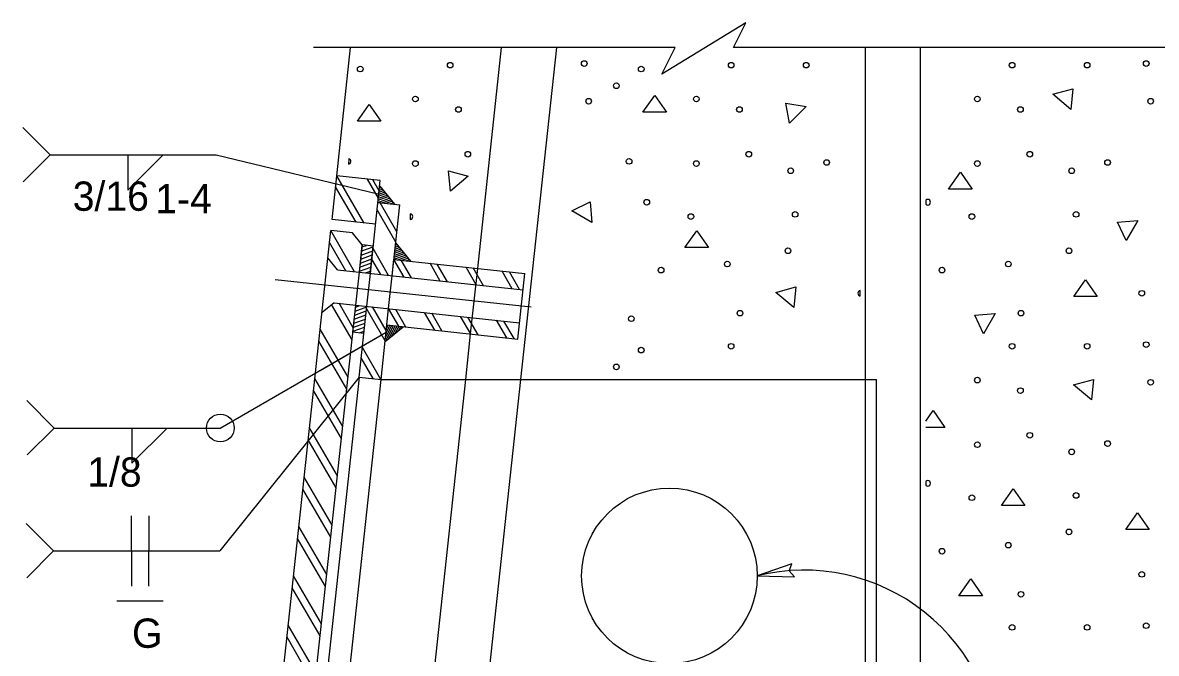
# Model space of a CAD drawing. Extents: x 0 to 2.83, y -0.03 to 1.83.
# Drawn here: x 2.1921 to 2.5956, y 0.6079 to 0.8323 of the extents above; entities that cross this region are included whole.
import ezdxf

# ---------------------------------------------------------------- set-up
doc = ezdxf.new("R2010")
doc.units = 0
for name, color, linetype in [('50', 7, 'Continuous'), ('51', 7, 'Continuous'), ('52', 7, 'Continuous'), ('54', 7, 'Continuous'), ('55', 7, 'Continuous'), ('57', 7, 'Continuous'), ('59', 7, 'Continuous')]:
    doc.layers.add(name, color=color, linetype=linetype)

msp = doc.modelspace()

# ---------------------------------------------------------------- linework, layer by layer
at = {"layer": '50'}
for p, q in [((2.3038940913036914, 0.7777618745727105), (2.3088182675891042, 0.8233925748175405)), ((2.3196378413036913, 0.7053306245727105), (2.4959440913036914, 0.7053306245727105)), ((2.4959440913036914, 0.4241493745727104), (2.4959440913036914, 0.7053306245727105))]:
    msp.add_line(p, q, dxfattribs=at)
for points in [[(2.558756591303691, 0.8067806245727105), (2.565806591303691, 0.8086806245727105), (2.5651565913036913, 0.8013806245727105), (2.558756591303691, 0.8067806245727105)], [(2.3113065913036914, 0.7971806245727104), (2.315456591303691, 0.8031306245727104), (2.319606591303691, 0.7971806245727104), (2.3113065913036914, 0.7971806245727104)], [(2.4128565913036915, 0.8003806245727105), (2.4170565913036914, 0.8063806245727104), (2.421206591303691, 0.8003806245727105), (2.4128565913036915, 0.8003806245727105)], [(2.4650565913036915, 0.7964806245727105), (2.4637565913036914, 0.8036806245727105), (2.4709565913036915, 0.8023806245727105), (2.4650565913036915, 0.7964806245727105)], [(2.308194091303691, 0.7838806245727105), (2.308019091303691, 0.7819181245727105)], [(2.3443065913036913, 0.7723306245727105), (2.343656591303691, 0.7795806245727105), (2.350706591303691, 0.7776806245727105), (2.3443065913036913, 0.7723306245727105)], [(2.5216565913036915, 0.7730806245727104), (2.5258565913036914, 0.7790806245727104), (2.530006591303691, 0.7730806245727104), (2.5216565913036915, 0.7730806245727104)], [(2.3875065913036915, 0.7653806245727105), (2.394106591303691, 0.7684806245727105), (2.394706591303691, 0.7612306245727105), (2.3875065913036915, 0.7653806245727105)], [(2.513500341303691, 0.7690931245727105), (2.513500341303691, 0.7676806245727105)], [(2.3300440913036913, 0.7642743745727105), (2.3300440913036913, 0.7622868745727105)], [(2.5848065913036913, 0.7547306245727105), (2.5817065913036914, 0.7613306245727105), (2.5889565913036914, 0.7619306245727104), (2.5848065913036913, 0.7547306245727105)], [(2.4278065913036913, 0.7522306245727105), (2.4320065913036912, 0.7582306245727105), (2.4361565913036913, 0.7522306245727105), (2.4278065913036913, 0.7522306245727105)], [(2.5661565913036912, 0.7348306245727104), (2.5703065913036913, 0.7408306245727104), (2.5745065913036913, 0.7348306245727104), (2.5661565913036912, 0.7348306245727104)], [(2.4602065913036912, 0.7363306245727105), (2.4672565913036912, 0.7382306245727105), (2.4666065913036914, 0.7309806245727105), (2.4602065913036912, 0.7363306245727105)], [(2.4901503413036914, 0.7350181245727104), (2.490169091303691, 0.7369681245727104)], [(2.5341065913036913, 0.7215806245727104), (2.5310065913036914, 0.7281806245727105), (2.5382565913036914, 0.7287806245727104), (2.5341065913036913, 0.7215806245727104)], [(2.5661065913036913, 0.7034306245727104), (2.5731565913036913, 0.7053306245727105), (2.5725065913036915, 0.6980806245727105), (2.5661065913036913, 0.7034306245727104)], [(2.513500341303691, 0.6905118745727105), (2.5161065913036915, 0.6942806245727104), (2.520256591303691, 0.6882806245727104), (2.513500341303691, 0.6882806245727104)], [(2.513500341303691, 0.6690931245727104), (2.513500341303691, 0.6676806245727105)], [(2.540456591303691, 0.6604806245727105), (2.5446065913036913, 0.6664306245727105), (2.5487565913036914, 0.6604806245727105), (2.540456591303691, 0.6604806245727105)], [(2.5847065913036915, 0.6519806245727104), (2.5889065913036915, 0.6579306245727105), (2.593056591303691, 0.6519806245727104), (2.5847065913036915, 0.6519806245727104)], [(2.5253065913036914, 0.6283806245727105), (2.5295065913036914, 0.6343806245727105), (2.5336565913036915, 0.6283806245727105), (2.5253065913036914, 0.6283806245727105)]]:
    msp.add_lwpolyline(points, dxfattribs=at)
for centre in [(2.31224447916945, 0.8157648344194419), (2.34424947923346, 0.8171390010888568), (2.3919628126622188, 0.8177281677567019), (2.412244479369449, 0.8157648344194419), (2.444249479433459, 0.8171390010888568), (2.4709536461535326, 0.8171390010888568), (2.5442494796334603, 0.8171390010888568), (2.5709536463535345, 0.8171390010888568), (2.591962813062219, 0.8177281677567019), (2.4034086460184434, 0.809816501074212), (2.331879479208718, 0.8051040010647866), (2.3935336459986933, 0.8043190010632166), (2.4318794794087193, 0.8051040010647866), (2.531879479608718, 0.8051040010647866), (2.5935336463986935, 0.8043190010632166), (2.347195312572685, 0.8013731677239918), (2.4471953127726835, 0.8013731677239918), (2.547195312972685, 0.8013731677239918), (2.331879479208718, 0.7821315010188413), (2.3505328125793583, 0.7854690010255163), (2.4079244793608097, 0.7829165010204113), (2.4318794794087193, 0.7821315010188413), (2.45053281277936, 0.7854690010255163), (2.478218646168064, 0.7825240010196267), (2.531879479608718, 0.7821315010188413), (2.5505328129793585, 0.7854690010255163), (2.5782186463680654, 0.7825240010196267), (2.465455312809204, 0.7795781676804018), (2.5654553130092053, 0.7795781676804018), (2.414207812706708, 0.7683865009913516), (2.4299161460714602, 0.7632815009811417), (2.4670261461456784, 0.7640665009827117), (2.5299161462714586, 0.7632815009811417), (2.56702614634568, 0.7640665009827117), (2.464473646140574, 0.7511081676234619), (2.5644736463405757, 0.7511081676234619), (2.4428753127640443, 0.7463956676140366), (2.542875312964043, 0.7463956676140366), (2.4193128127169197, 0.7442356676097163), (2.519312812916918, 0.7442356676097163), (2.5903919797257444, 0.7359890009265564), (2.4087103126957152, 0.7269565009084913), (2.447391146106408, 0.7289198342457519), (2.5473911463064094, 0.7289198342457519), (2.591962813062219, 0.7177281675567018), (2.412244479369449, 0.7157648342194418), (2.444249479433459, 0.7171390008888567), (2.5442494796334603, 0.7171390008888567), (2.5709536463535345, 0.7171390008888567), (2.4034086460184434, 0.7098165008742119), (2.531879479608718, 0.7051040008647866), (2.547195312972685, 0.7013731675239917), (2.5935336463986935, 0.7043190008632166), (2.5505328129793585, 0.6854690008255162), (2.531879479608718, 0.6821315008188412), (2.5782186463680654, 0.6825240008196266), (2.5654553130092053, 0.6795781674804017), (2.5299161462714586, 0.6632815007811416), (2.56702614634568, 0.6640665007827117), (2.5644736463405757, 0.6511081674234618), (2.542875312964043, 0.6463956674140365), (2.519312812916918, 0.6442356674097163), (2.5903919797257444, 0.6359890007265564), (2.5473911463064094, 0.6289198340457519), (2.5442494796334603, 0.6171390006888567), (2.5709536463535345, 0.6171390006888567), (2.591962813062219, 0.6177281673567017)]:
    msp.add_circle(centre, 0.0010011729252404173, dxfattribs=at)
for centre, start, end in [((2.3079244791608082, 0.7829165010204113), 275.39363055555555, 74.22253333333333), ((2.51420781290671, 0.7683865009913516), 225.03758611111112, 134.96241388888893), ((2.3299161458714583, 0.7632815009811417), 277.34222222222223, 82.65777500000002), ((2.490391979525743, 0.7359890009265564), 102.75421944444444, 256.04021111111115), ((2.51420781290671, 0.6683865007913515), 225.03758611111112, 134.96241388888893)]:
    msp.add_arc(centre, 0.0010011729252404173, start, end, dxfattribs=at)
at = {"layer": '51'}
for p, q in [((2.3623987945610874, 0.8233925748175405), (2.353919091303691, 0.7448368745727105)), ((2.382049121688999, 0.8233925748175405), (2.3693065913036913, 0.7053306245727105)), ((2.4919940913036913, 0.8233925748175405), (2.4919940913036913, 0.7053306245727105)), ((2.5115378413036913, 0.8233925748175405), (2.5115378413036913, 0.3265870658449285)), ((2.353919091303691, 0.7448368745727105), (2.3514065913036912, 0.7215431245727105)), ((2.3514065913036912, 0.7215431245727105), (2.3496565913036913, 0.7053306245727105)), ((2.3496565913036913, 0.7053306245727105), (2.3193003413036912, 0.4241493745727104)), ((2.3693065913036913, 0.7053306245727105), (2.338950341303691, 0.4241493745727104)), ((2.4919940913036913, 0.7053306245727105), (2.4919940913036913, 0.4241493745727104))]:
    msp.add_line(p, q, dxfattribs=at)
at = {"layer": '52'}
for p, q in [((2.3021940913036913, 0.7621868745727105), (2.3038940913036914, 0.7777618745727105)), ((2.3193878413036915, 0.7760618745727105), (2.3038940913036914, 0.7777618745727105)), ((2.3135815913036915, 0.7609806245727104), (2.3038940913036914, 0.7777618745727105)), ((2.3187128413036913, 0.7698368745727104), (2.314831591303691, 0.7765618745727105)), ((2.3158378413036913, 0.7430618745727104), (2.3193878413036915, 0.7760618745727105)), ((2.3189940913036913, 0.7724306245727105), (2.316731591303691, 0.7763493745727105)), ((2.310739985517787, 0.7612782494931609), (2.303468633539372, 0.7738639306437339)), ((2.3187065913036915, 0.7697868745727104), (2.3217690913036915, 0.7709056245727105)), ((2.318787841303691, 0.7705056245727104), (2.321344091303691, 0.7714368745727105)), ((2.3188628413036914, 0.7712306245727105), (2.3209128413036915, 0.7719681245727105)), ((2.3189440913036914, 0.7719431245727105), (2.3204815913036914, 0.7725056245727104)), ((2.319031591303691, 0.7726681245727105), (2.3200440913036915, 0.7730431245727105)), ((2.3191065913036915, 0.7733868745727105), (2.319619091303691, 0.7735806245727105)), ((2.3191878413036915, 0.7741118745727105), (2.3243878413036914, 0.7676618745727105)), ((2.3191878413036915, 0.7741118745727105), (2.3191878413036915, 0.7741118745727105)), ((2.3185378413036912, 0.7683431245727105), (2.3226378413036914, 0.7698368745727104)), ((2.3185378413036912, 0.7683118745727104), (2.3263378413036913, 0.7674368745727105)), ((2.3186190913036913, 0.7690618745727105), (2.3222065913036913, 0.7703681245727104)), ((2.325305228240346, 0.7578804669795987), (2.319334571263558, 0.7682224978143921)), ((2.3199315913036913, 0.7681556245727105), (2.323069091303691, 0.7692931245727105)), ((2.3213878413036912, 0.7679993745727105), (2.3234940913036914, 0.7687618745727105)), ((2.322844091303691, 0.7678368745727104), (2.323925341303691, 0.7682306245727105)), ((2.3236128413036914, 0.7422181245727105), (2.3263378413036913, 0.7674368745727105)), ((2.3242940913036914, 0.7676743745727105), (2.3243628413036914, 0.7676993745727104)), ((2.3248940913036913, 0.7541993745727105), (2.3182440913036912, 0.7657243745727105)), ((2.3177128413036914, 0.7605368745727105), (2.3021940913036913, 0.7621868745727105)), ((2.2605753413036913, 0.3766618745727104), (2.3017940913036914, 0.7583181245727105)), ((2.309506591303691, 0.7574806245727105), (2.3017940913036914, 0.7583181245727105)), ((2.3102503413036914, 0.7436618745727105), (2.3017940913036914, 0.7583181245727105)), ((2.3129753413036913, 0.7531806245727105), (2.309506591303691, 0.7574806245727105)), ((2.307137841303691, 0.7439993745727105), (2.301331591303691, 0.7540493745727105)), ((2.311925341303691, 0.7434868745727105), (2.3129753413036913, 0.7531806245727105)), ((2.3119378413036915, 0.7434743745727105), (2.3129878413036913, 0.7531931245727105)), ((2.3126003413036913, 0.7495931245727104), (2.3166940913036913, 0.7510868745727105)), ((2.312756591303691, 0.7510368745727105), (2.3168565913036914, 0.7525243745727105)), ((2.3129128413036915, 0.7524743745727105), (2.3144378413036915, 0.7530243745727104)), ((2.3168878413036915, 0.7527681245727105), (2.3129878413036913, 0.7531931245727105)), ((2.3129878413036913, 0.7531931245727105), (2.3129878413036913, 0.7531931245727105)), ((2.315831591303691, 0.7430618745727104), (2.3168878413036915, 0.7527681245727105)), ((2.322349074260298, 0.7423515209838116), (2.3167962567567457, 0.7519710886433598)), ((2.3244003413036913, 0.7495431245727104), (2.3274690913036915, 0.7506618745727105)), ((2.324487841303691, 0.7502618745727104), (2.327044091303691, 0.7511931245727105)), ((2.3245628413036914, 0.7509868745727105), (2.3266128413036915, 0.7517243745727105)), ((2.3246440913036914, 0.7516993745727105), (2.326175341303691, 0.7522556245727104)), ((2.3247253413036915, 0.7524243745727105), (2.325744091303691, 0.7527993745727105)), ((2.3248003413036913, 0.7531431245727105), (2.325319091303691, 0.7533306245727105)), ((2.324887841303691, 0.7538681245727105), (2.3300878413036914, 0.7474181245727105)), ((2.324887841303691, 0.7538681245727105), (2.324887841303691, 0.7538681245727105)), ((2.324887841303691, 0.7538681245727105), (2.324887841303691, 0.7538681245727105)), ((2.324887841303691, 0.7538681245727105), (2.324887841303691, 0.7538681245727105)), ((2.304194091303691, 0.7443181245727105), (2.300744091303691, 0.7486181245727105)), ((2.3121315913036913, 0.7452743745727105), (2.3162315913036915, 0.7467681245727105)), ((2.312287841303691, 0.7467118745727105), (2.3163878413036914, 0.7481993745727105)), ((2.312450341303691, 0.7481493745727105), (2.3165378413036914, 0.7496431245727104)), ((2.319537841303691, 0.7426618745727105), (2.3163628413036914, 0.7481618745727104)), ((2.3235878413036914, 0.7422181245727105), (2.324219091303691, 0.7480681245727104)), ((2.3242378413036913, 0.7480993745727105), (2.3283378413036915, 0.7495931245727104)), ((2.3242378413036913, 0.7480681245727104), (2.3708253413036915, 0.7429931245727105)), ((2.3278753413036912, 0.7417556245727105), (2.3242378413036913, 0.7480681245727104)), ((2.3243190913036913, 0.7488181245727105), (2.327900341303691, 0.7501243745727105)), ((2.325625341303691, 0.7479118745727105), (2.328769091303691, 0.7490493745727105)), ((2.3304503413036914, 0.7414806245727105), (2.3268128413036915, 0.7477868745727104)), ((2.3270878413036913, 0.7477493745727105), (2.3291940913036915, 0.7485181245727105)), ((2.328544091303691, 0.7475931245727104), (2.329625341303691, 0.7479868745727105)), ((2.3299940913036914, 0.7474243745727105), (2.3300628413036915, 0.7474493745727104)), ((2.3407065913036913, 0.7403618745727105), (2.3370690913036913, 0.7466681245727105)), ((2.304194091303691, 0.7443181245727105), (2.370200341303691, 0.7371681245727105)), ((2.3106753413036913, 0.7318118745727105), (2.3119378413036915, 0.7434743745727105)), ((2.311981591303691, 0.7438368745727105), (2.3160690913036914, 0.7453243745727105)), ((2.3141503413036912, 0.7432431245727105), (2.3159190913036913, 0.7438868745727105)), ((2.3145690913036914, 0.7313868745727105), (2.3158378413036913, 0.7430618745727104)), ((2.3156128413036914, 0.7430868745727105), (2.3158378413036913, 0.7431681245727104)), ((2.3432753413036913, 0.7400868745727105), (2.3396378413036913, 0.7463868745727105)), ((2.3535378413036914, 0.7389806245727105), (2.349894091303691, 0.7452743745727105)), ((2.356100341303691, 0.7386931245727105), (2.3524690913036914, 0.7449931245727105)), ((2.3663690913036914, 0.7375868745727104), (2.3627378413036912, 0.7438743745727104)), ((2.3689315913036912, 0.7373056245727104), (2.3653065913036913, 0.7435931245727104)), ((2.368275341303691, 0.7197243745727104), (2.3708253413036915, 0.7429931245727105)), ((2.3223565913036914, 0.7305493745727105), (2.323619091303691, 0.7422118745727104)), ((2.274925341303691, 0.4006618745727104), (2.3106628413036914, 0.7318118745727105)), ((2.3029440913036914, 0.7326493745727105), (2.298644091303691, 0.7291993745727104)), ((2.3093253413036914, 0.7193743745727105), (2.302069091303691, 0.7319493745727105)), ((2.3029440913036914, 0.7326493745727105), (2.3689253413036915, 0.7255243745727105)), ((2.3097815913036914, 0.7236493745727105), (2.3047003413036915, 0.7324556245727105)), ((2.309637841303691, 0.7221243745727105), (2.310681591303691, 0.7318118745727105)), ((2.3104378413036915, 0.7296556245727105), (2.3145565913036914, 0.7311556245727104)), ((2.310587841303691, 0.7310993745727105), (2.3121315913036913, 0.7316556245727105)), ((2.3106628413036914, 0.7318118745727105), (2.3106628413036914, 0.7318118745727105)), ((2.3118628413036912, 0.7061806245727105), (2.3145815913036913, 0.7313868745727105)), ((2.3135128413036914, 0.7216993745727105), (2.3145690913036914, 0.7313868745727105)), ((2.3211128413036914, 0.7190931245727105), (2.314481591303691, 0.7305868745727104)), ((2.3215155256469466, 0.7227477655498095), (2.316646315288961, 0.731169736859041)), ((2.3196378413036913, 0.7053306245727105), (2.3223565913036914, 0.7305493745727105)), ((2.321706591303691, 0.7247243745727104), (2.3223315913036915, 0.7305556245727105)), ((2.3259503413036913, 0.7242743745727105), (2.3223190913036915, 0.7305556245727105)), ((2.3285190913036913, 0.7239931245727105), (2.3248940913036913, 0.7302806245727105)), ((2.3099815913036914, 0.7253431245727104), (2.3140878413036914, 0.7268368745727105)), ((2.3101315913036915, 0.7267806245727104), (2.3142503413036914, 0.7282743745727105)), ((2.310281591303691, 0.7282118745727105), (2.314400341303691, 0.7297118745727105)), ((2.338775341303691, 0.7228931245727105), (2.335150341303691, 0.7291743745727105)), ((2.3413378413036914, 0.7226181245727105), (2.337719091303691, 0.7288868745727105)), ((2.3515878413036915, 0.7215181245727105), (2.3479690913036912, 0.7277868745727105)), ((2.3541628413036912, 0.7212431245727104), (2.3505440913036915, 0.7275056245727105)), ((2.364406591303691, 0.7201431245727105), (2.360794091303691, 0.7263993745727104)), ((2.307887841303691, 0.7061056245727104), (2.298000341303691, 0.7232243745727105)), ((2.3096753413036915, 0.7224681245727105), (2.3137815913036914, 0.7239556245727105)), ((2.3098315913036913, 0.7238993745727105), (2.3139378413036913, 0.7253993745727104)), ((2.311875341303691, 0.7218806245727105), (2.3136315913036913, 0.7225181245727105)), ((2.3211128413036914, 0.7188743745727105), (2.3275628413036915, 0.7240743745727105)), ((2.3228190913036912, 0.7202493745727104), (2.321506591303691, 0.7225306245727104)), ((2.323325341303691, 0.7206681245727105), (2.3216190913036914, 0.7236243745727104)), ((2.3217378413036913, 0.7247243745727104), (2.368275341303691, 0.7197243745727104)), ((2.3238440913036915, 0.7210743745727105), (2.3217378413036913, 0.7247243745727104)), ((2.3243503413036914, 0.7214931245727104), (2.3225378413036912, 0.7246306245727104)), ((2.3248690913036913, 0.7218993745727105), (2.3233440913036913, 0.7245493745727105)), ((2.3253753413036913, 0.7223181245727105), (2.3241440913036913, 0.7244556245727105)), ((2.325894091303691, 0.7227243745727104), (2.324944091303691, 0.7243681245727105)), ((2.326400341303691, 0.7231431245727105), (2.325744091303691, 0.7242743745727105)), ((2.3269190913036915, 0.7235556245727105), (2.326550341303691, 0.7241931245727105)), ((2.3274253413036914, 0.7239681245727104), (2.327350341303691, 0.7240993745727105)), ((2.3669815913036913, 0.7198556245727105), (2.3633690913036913, 0.7261243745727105)), ((2.307431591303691, 0.7018306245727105), (2.297544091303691, 0.7189556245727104)), ((2.3135128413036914, 0.7216993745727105), (2.309637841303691, 0.7221243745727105)), ((2.3133378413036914, 0.7217243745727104), (2.3135503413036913, 0.7217993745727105)), ((2.3212815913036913, 0.7190056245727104), (2.321156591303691, 0.7192431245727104)), ((2.3217940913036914, 0.7194243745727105), (2.3212690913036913, 0.7203306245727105)), ((2.322306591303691, 0.7198431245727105), (2.3213878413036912, 0.7214306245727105)), ((2.3195310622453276, 0.7053422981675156), (2.3129946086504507, 0.7166735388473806)), ((2.316862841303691, 0.7056306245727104), (2.3126003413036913, 0.7130243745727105)), ((2.3118628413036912, 0.7061806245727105), (2.2815440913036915, 0.4254993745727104)), ((2.3118628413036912, 0.7061806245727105), (2.3196378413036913, 0.7053306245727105)), ((2.289344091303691, 0.4246243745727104), (2.3196378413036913, 0.7053306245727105)), ((2.3059940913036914, 0.6885493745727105), (2.296112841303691, 0.7056806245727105)), ((2.305544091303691, 0.6842868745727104), (2.2956503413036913, 0.7014056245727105)), ((2.304100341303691, 0.6710056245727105), (2.2942128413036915, 0.6881306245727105)), ((2.3036440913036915, 0.6667368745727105), (2.2937628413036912, 0.6838618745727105)), ((2.3022065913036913, 0.6534556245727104), (2.2923190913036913, 0.6705868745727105)), ((2.3017503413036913, 0.6491868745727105), (2.2918628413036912, 0.6663118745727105)), ((2.3003065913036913, 0.6359118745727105), (2.2904190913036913, 0.6530431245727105)), ((2.2998565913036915, 0.6316368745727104), (2.2899690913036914, 0.6487681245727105)), ((2.2984190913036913, 0.6183556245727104), (2.288531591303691, 0.6354868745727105)), ((2.2979565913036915, 0.6140931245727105), (2.2880690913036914, 0.6312243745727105)), ((2.2965253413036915, 0.6008118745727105), (2.2866378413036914, 0.6179431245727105)), ((2.2960690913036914, 0.5965493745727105), (2.2861815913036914, 0.6136743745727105))]:
    msp.add_line(p, q, dxfattribs=at)
msp.add_circle((2.422287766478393, 0.6354544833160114), 0.03125, dxfattribs=at)
at = {"layer": '54'}
msp.add_lwpolyline([(2.453537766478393, 0.6354544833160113), (2.4667398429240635, 0.6350950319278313), (2.464885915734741, 0.637211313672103), (2.4658610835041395, 0.6397908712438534)], close=True, dxfattribs=at)
at = {"layer": '55'}
for p, q in [((2.4494315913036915, 0.8322550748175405), (2.4195940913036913, 0.8139300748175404)), ((2.445100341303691, 0.8233925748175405), (2.4494315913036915, 0.8322550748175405)), ((2.424337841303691, 0.8233925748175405), (2.2955690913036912, 0.8233925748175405)), ((2.4195940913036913, 0.8139300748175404), (2.424337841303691, 0.8233925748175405)), ((2.6166065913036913, 0.8233925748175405), (2.445100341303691, 0.8233925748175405)), ((2.373050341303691, 0.7309993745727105), (2.2819565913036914, 0.7408306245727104))]:
    msp.add_line(p, q, dxfattribs=at)
msp.add_arc((2.4702347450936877, 0.5686022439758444), 0.06890581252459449, 359.00073136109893, 104.0232710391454, dxfattribs=at)
at = {"layer": '57'}
for p, q in [((2.19210142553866, 0.7949780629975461), (2.2018759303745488, 0.7852035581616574)), ((2.192297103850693, 0.7756247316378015), (2.2018759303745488, 0.7852035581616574)), ((2.2018759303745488, 0.7852035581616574), (2.2609734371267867, 0.7852035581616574)), ((2.2358071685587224, 0.7852035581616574), (2.2358071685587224, 0.7852035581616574)), ((2.2609734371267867, 0.7852035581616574), (2.3185253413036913, 0.7713556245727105)), ((2.2624253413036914, 0.6880618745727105), (2.3214690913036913, 0.7221493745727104)), ((2.3118628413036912, 0.7061806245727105), (2.2622128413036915, 0.6443368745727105)), ((2.1935533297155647, 0.6978363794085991), (2.2033278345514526, 0.6880618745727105)), ((2.1937490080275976, 0.6784830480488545), (2.2033278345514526, 0.6880618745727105)), ((2.2033278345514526, 0.6880618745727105), (2.2624253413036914, 0.6880618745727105)), ((2.2372590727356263, 0.6880618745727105), (2.2372590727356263, 0.6880618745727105)), ((2.1933408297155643, 0.6541113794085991), (2.2031153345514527, 0.6443368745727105)), ((2.2307965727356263, 0.6443368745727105), (2.2307965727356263, 0.6568368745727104)), ((2.2370465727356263, 0.6568368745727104), (2.2370465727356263, 0.6443368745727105)), ((2.1935365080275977, 0.6347580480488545), (2.2031153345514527, 0.6443368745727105)), ((2.2031153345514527, 0.6443368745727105), (2.2622128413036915, 0.6443368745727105)), ((2.2307965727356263, 0.6443368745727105), (2.2307965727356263, 0.6318368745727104)), ((2.2370465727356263, 0.6443368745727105), (2.2370465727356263, 0.6443368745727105)), ((2.2370465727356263, 0.6443368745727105), (2.2370465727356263, 0.6443368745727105)), ((2.2370465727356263, 0.6318368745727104), (2.2370465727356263, 0.6443368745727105)), ((2.2370465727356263, 0.6443368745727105), (2.2370465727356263, 0.6443368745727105)), ((2.2370465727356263, 0.6443368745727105), (2.2370465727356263, 0.6443368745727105)), ((2.2256663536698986, 0.6265868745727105), (2.2420663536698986, 0.6265868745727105)), ((2.2338663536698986, 0.6265868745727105), (2.2338663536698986, 0.6265868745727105))]:
    msp.add_line(p, q, dxfattribs=at)
for points in [[(2.2295571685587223, 0.7852035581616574), (2.2295571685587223, 0.7727035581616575), (2.242057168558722, 0.7852035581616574)], [(2.231009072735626, 0.6880618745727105), (2.231009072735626, 0.6755618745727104), (2.2435090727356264, 0.6880618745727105)]]:
    msp.add_lwpolyline(points, dxfattribs=at)
at = {"layer": '59'}
for p, q in [((2.2979440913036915, 0.7085681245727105), (2.3214690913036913, 0.7221493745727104)), ((2.2979440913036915, 0.6547368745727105), (2.2979440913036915, 0.6547368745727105))]:
    msp.add_line(p, q, dxfattribs=at)
msp.add_circle((2.2624253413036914, 0.6880618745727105), 0.004921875, dxfattribs=at)

# ---------------------------------------------------------------- texts
at = {"layer": '57'}
for s, height, p in [('3/16', 0.010416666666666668, (2.209910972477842, 0.7653364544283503)), ('1-4', 0.010416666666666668, (2.239302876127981, 0.7644394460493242)), ('1/8', 0.010416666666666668, (2.215066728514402, 0.6672095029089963)), ('G', 0.010416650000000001, (2.2310132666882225, 0.6098754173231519))]:
    msp.add_text(s, height=height, dxfattribs=at).set_placement(p)

doc.saveas('drawing.dxf')
